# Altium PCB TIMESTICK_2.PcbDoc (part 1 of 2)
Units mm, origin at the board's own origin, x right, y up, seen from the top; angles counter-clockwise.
Board outline 82 x 42 mm, 4 copper layers (Top Layer, Int1, Int2, Bottom Layer), stack 0.954 mm thick; 117 components, 82 nets, 437 pads, 366 vias.
Unrouted connection lines stored in the file: 51.
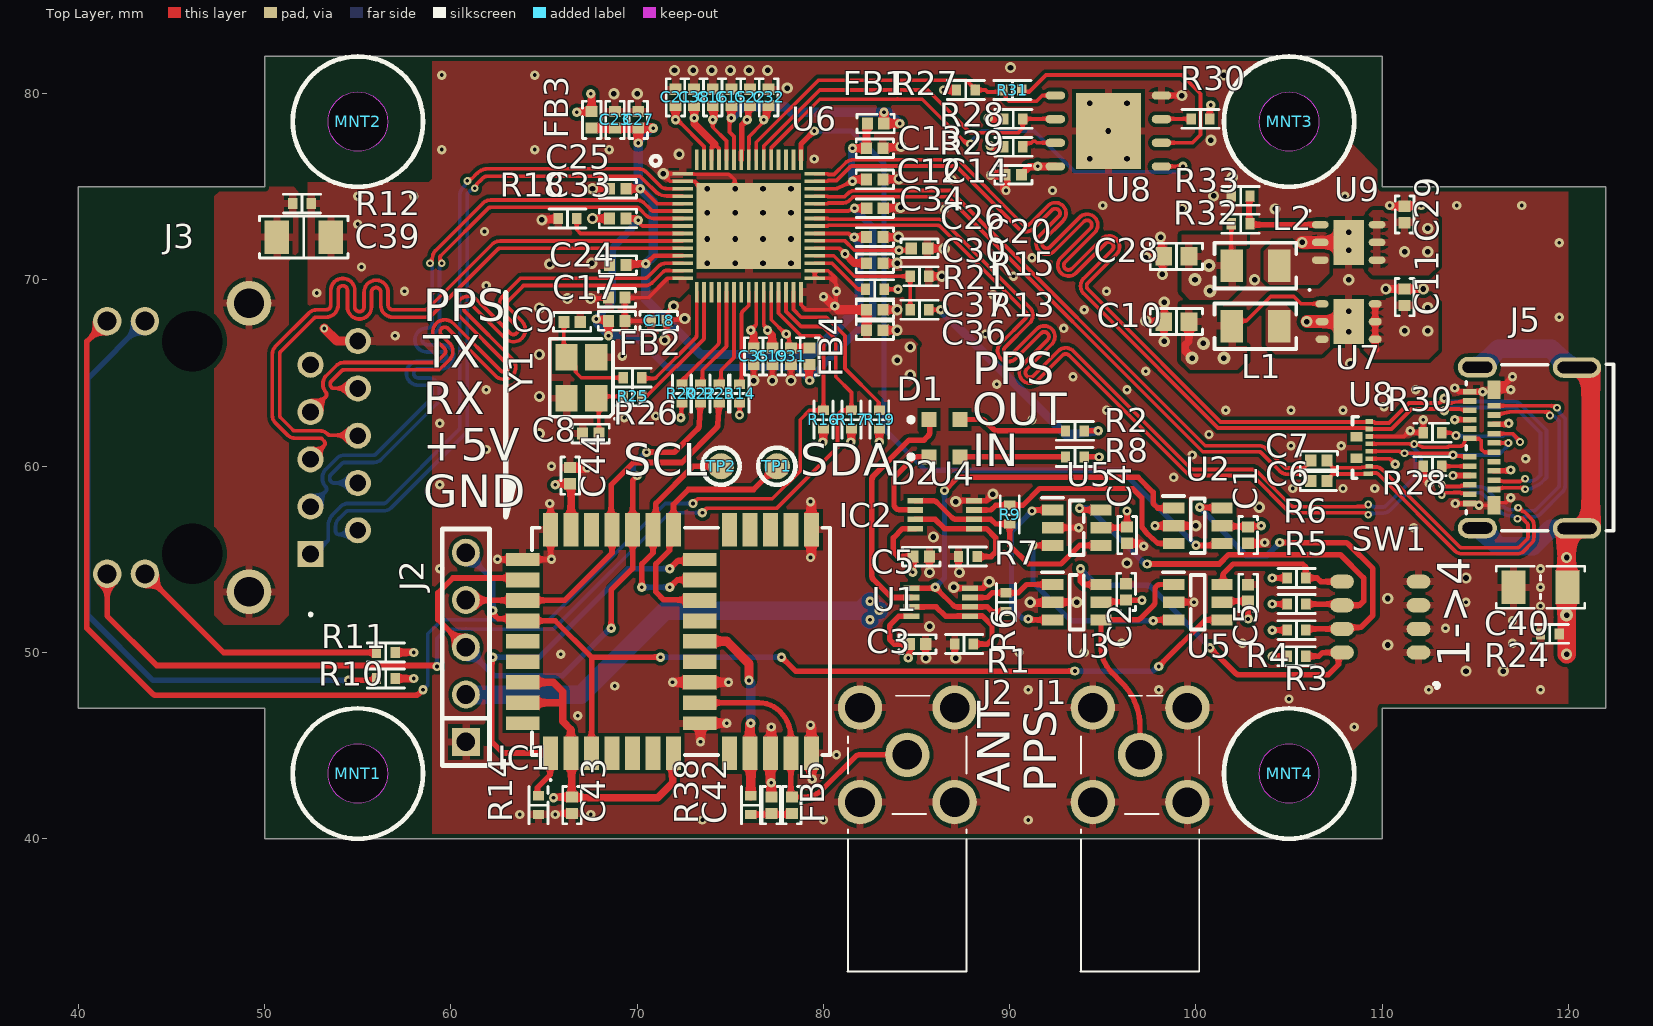
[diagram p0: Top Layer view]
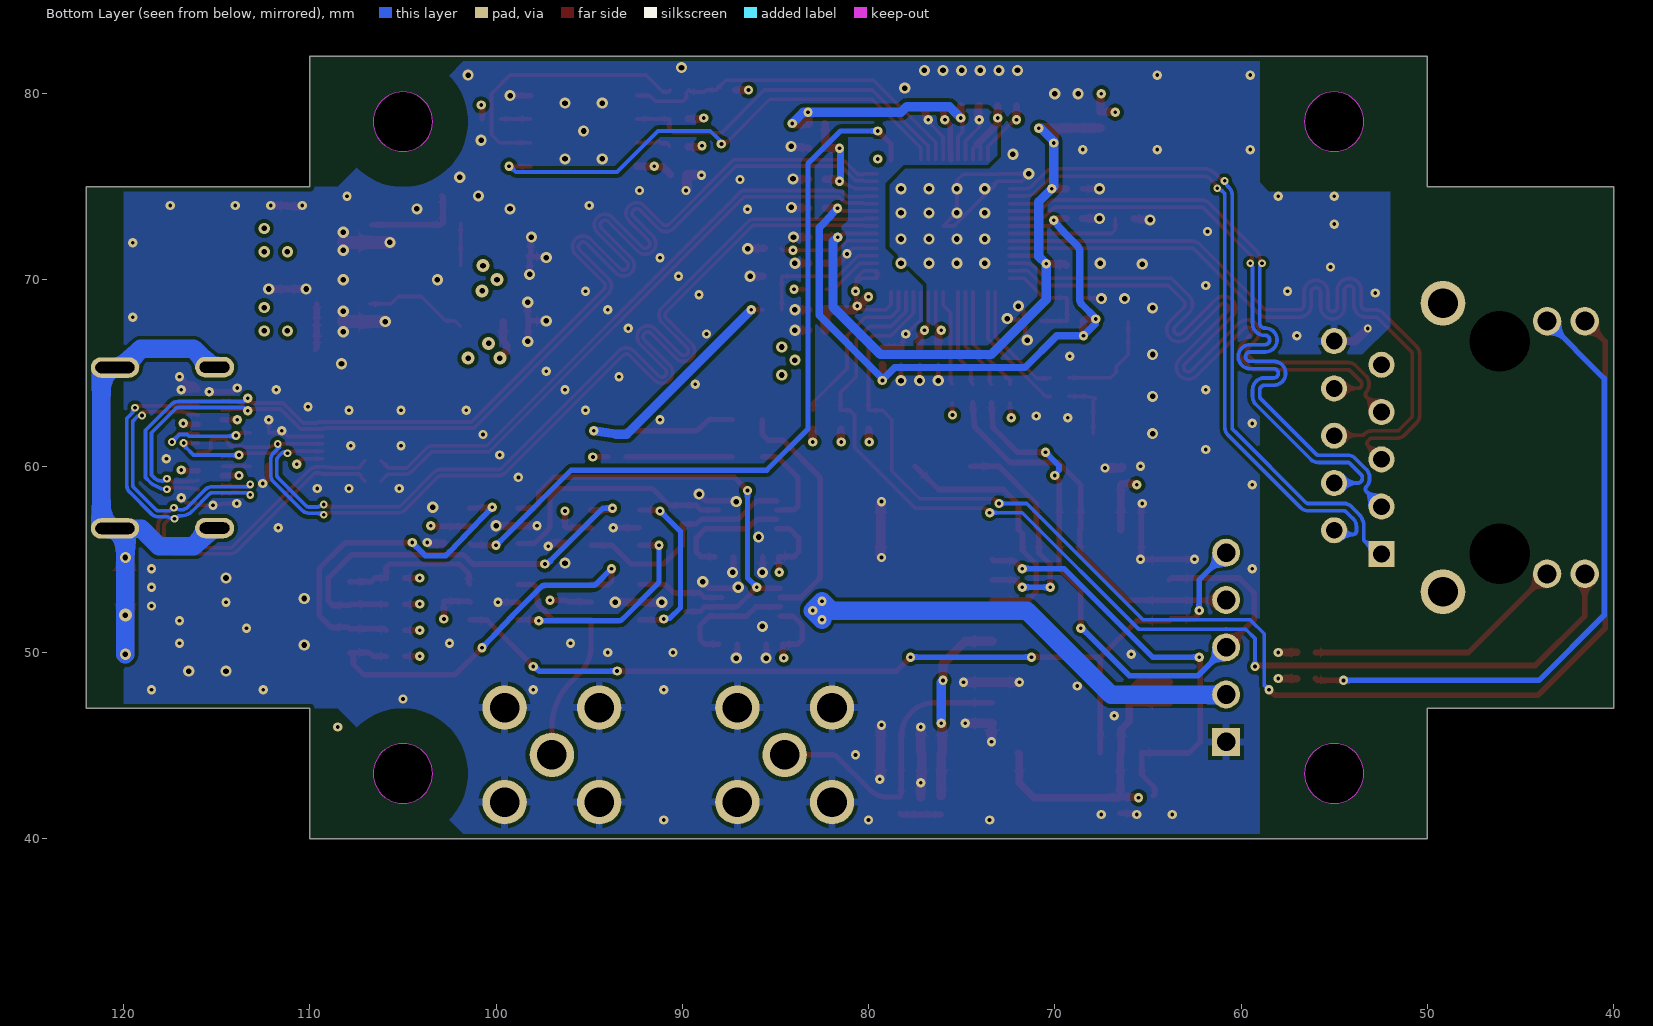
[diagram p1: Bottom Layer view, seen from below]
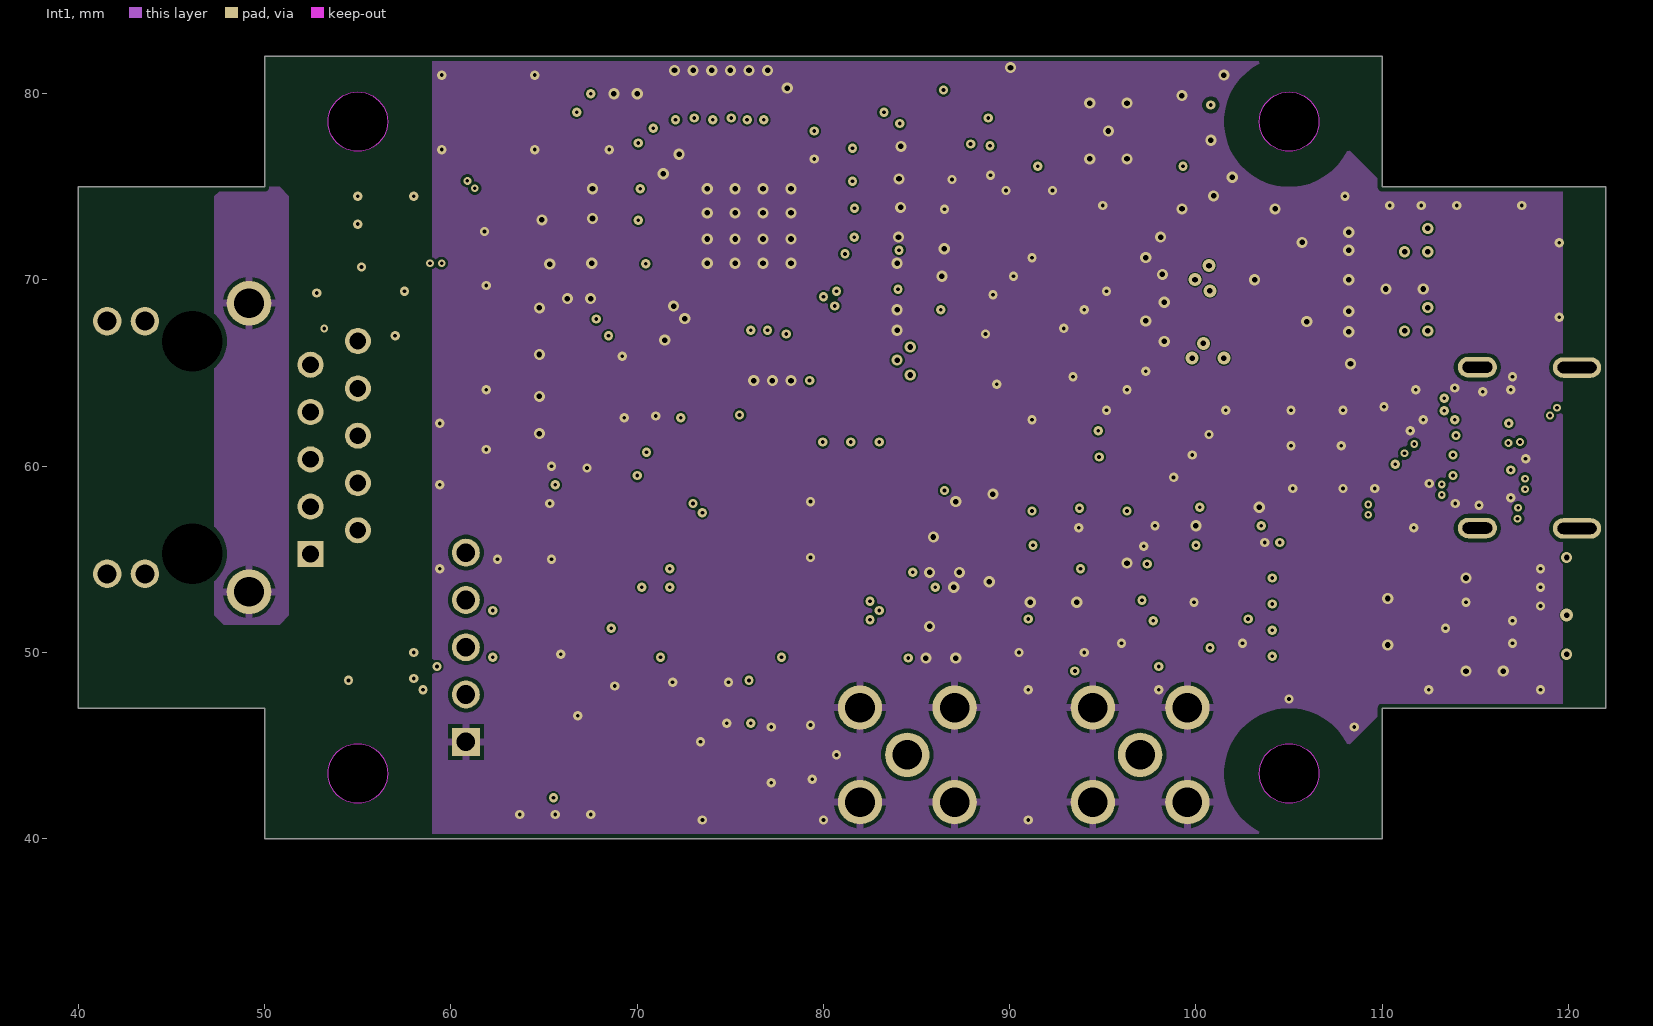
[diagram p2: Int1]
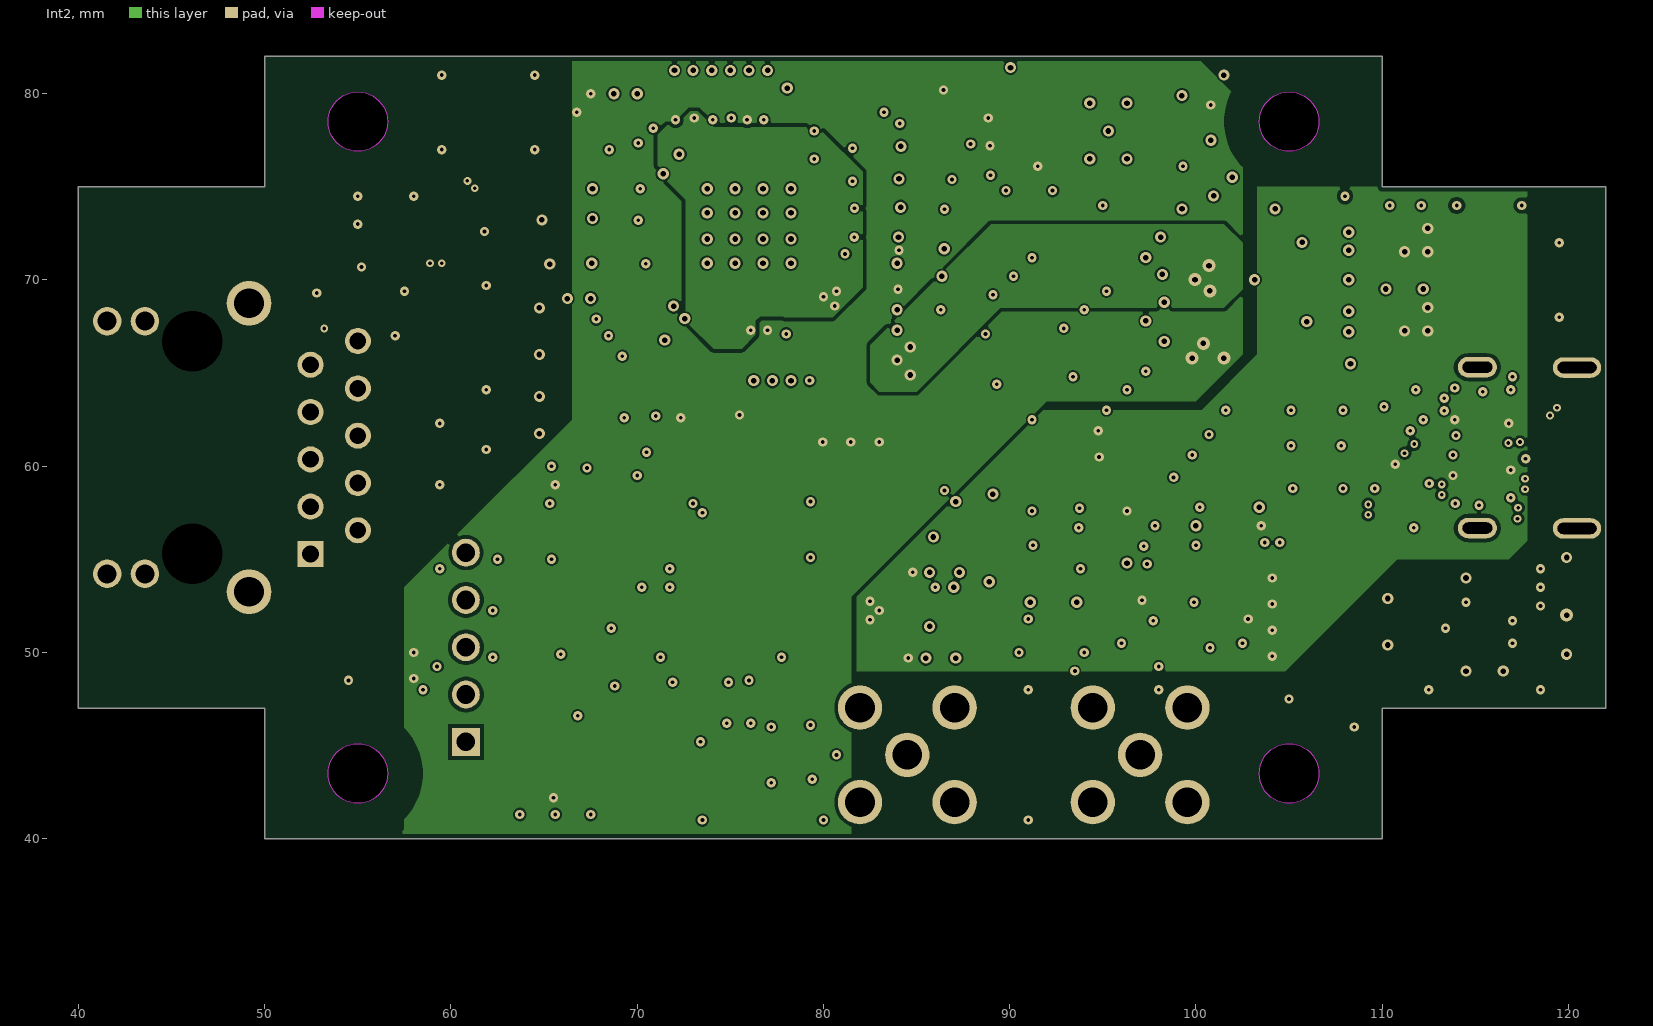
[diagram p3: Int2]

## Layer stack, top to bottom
Top Solder: solder mask 0.0254, SM-001, Dk 3.5
Top Layer: signal copper 0.035
Dielectric 1: prepreg 0.076, FR4, Dk 3.6
Dielectric 2: prepreg 0.076, FR4, Dk 3.6
Int1: signal copper 0.035
Dielectric 3: core 0.51, FR4, Dk 4.6
Int2: signal copper 0.035
Dielectric 4: prepreg 0.076, FR4, Dk 3.6
Dielectric 5: prepreg 0.076, FR4, Dk 3.6
Bottom Layer: signal copper 0.035
Bottom Solder: solder mask 0.0254, SM-001, Dk 3.5

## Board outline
40,47 50,47 50,40 110,40 110,47 122,47 122,75 110,75 110,82 50,82 50,75 40,75

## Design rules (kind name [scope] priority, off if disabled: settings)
AcuteAngle [All] p1: minimum=3.50000000000000E+0001 checktracksonly=FALSE
BoardOutlineClearance "BoardOutlineClearance 1" [All] p1: gap=0.25 ignorepadtopadclearanceinfootprint=FALSE except(0: Arc-SplitContinuation Track-SplitContinuation SMDPad-SplitContinuation THPad-SplitContinuation Via-SplitContinuation Fill-SplitContinuation Poly-SplitContinuation Region-SplitContinuation Text-SplitContinuation) // Milling
BoardOutlineClearance "BoardOutlineClearance 2" [All] p2: gap=0.4 ignorepadtopadclearanceinfootprint=FALSE except(0: Arc-SplitContinuation Track-SplitContinuation SMDPad-SplitContinuation THPad-SplitContinuation Via-SplitContinuation Fill-SplitContinuation Poly-SplitContinuation Region-SplitContinuation Text-SplitContinuation) // V-Cut
Clearance "Clearance 3 Oz" [All] p1 off: gap=0.35 ignorepadtopadclearanceinfootprint=FALSE except(0.25: Arc-Hole Track-Hole SMDPad-Hole THPad-Hole Via-Hole Fill-Hole Poly-Hole Region-Hole Text-Hole)
Clearance "Clearance 2 Oz" [All] p2 off: gap=0.3 ignorepadtopadclearanceinfootprint=FALSE except(0.25: Arc-Hole Track-Hole SMDPad-Hole THPad-Hole Via-Hole Fill-Hole Poly-Hole Region-Hole Text-Hole)
Clearance "Clearance-1 1 Oz" [All] p3 off: gap=0.2 ignorepadtopadclearanceinfootprint=FALSE except(0.25: Arc-Hole Track-Hole SMDPad-Hole THPad-Hole Via-Hole Fill-Hole Poly-Hole Region-Hole Text-Hole) // Standart
Clearance "Clearance-2 1 Oz" [All] p4 off: gap=0.15 ignorepadtopadclearanceinfootprint=FALSE except(0.2: Arc-Fill Arc-Poly Track-Fill Track-Poly SMDPad-Fill SMDPad-Poly THPad-Fill THPad-Poly Via-Fill Via-Poly Fill-Fill Fill-Poly Poly-Poly; 0.25: Arc-Hole Track-Hole SMDPad-Hole THPad-Hole Via-Hole Fill-Hole Poly-Hole Region-Hole Text-Hole) // Advance
Clearance "Clearance-1 1/2 Oz" [All] p5: gap=0.125 ignorepadtopadclearanceinfootprint=FALSE except(0.2: Arc-Fill Arc-Poly Track-Fill Track-Poly SMDPad-SMDPad SMDPad-Fill SMDPad-Poly THPad-Fill THPad-Poly Via-Fill Via-Poly Fill-Fill Fill-Poly Poly-Poly Poly-Region Poly-Text; 0.25: Arc-Hole Track-Hole SMDPad-Hole THPad-Hole Via-Hole Fill-Hole Poly-Hole Region-Hole Text-Hole) // Standart
Clearance "Clearance-2 1/2 Oz" [All] p6 off: gap=0.1 ignorepadtopadclearanceinfootprint=FALSE except(0.15: Arc-Fill Arc-Poly Track-Fill Track-Poly SMDPad-SMDPad SMDPad-Fill SMDPad-Poly THPad-Fill THPad-Poly Via-Fill Via-Poly Fill-Fill Fill-Poly Poly-Poly Poly-Region Poly-Text; 0.25: Arc-Hole Track-Hole SMDPad-Hole THPad-Hole Via-Hole Fill-Hole Poly-Hole Region-Hole Text-Hole) // Advance
DiffPairsRouting "DiffPairsRouting D90" [InDifferentialPairClass('D90')] p1: maxlimit=0.127 minlimit=0.124 mostfreqgap=0.127 toplayer_mingap=0.125 toplayer_maxgap=0.125 toplayer_prefgap=0.125 toplayer_minwidth=0.2 toplayer_maxwidth=0.2 toplayer_prefwidth=0.2 bottomlayer_mingap=0.125 bottomlayer_maxgap=0.125 bottomlayer_prefgap=0.125 bottomlayer_minwidth=0.2 bottomlayer_maxwidth=0.2 bottomlayer_prefwidth=0.2 impedanceprofiledriven=TRUE impedanceprofileid={4E89E9AB-B508-4CAD-8FE7-DB52ABFAAFB0} impedanceprofilevalue=90.000000 maxuncoupledlength=12.7
DiffPairsRouting "DiffPairsRouting D100" [InDifferentialPairClass('D100')] p2: maxlimit=0.203 minlimit=0.127 mostfreqgap=0.203 toplayer_mingap=0.194 toplayer_maxgap=0.194 toplayer_prefgap=0.194 toplayer_minwidth=0.2 toplayer_maxwidth=0.2 toplayer_prefwidth=0.2 bottomlayer_mingap=0.194 bottomlayer_maxgap=0.194 bottomlayer_prefgap=0.194 bottomlayer_minwidth=0.2 bottomlayer_maxwidth=0.2 bottomlayer_prefwidth=0.2 impedanceprofiledriven=TRUE impedanceprofileid={D171256F-88BE-4059-8FC0-C341FC197521} impedanceprofilevalue=100.000000 maxuncoupledlength=12.7
HoleSize "Minimum HoleSize" [IsPad] p1: absolutevalues=TRUE maxlimit=5.9 minlimit=0.6 maxpercent=80.000 minpercent=20.000
HoleSize "Minimum HoleSize VIA 1" [IsVia] p2 off: absolutevalues=TRUE maxlimit=5.9 minlimit=0.3 maxpercent=80.000 minpercent=20.000 // Standart
HoleSize "Minimum HoleSize VIA 2" [IsVia] p3: absolutevalues=TRUE maxlimit=5.9 minlimit=0.2 maxpercent=80.000 minpercent=20.000 // Advance
HoleToHoleClearance Hole2HoleClearance [All] p1: gap=0.25 allowstackedmicrovias=FALSE
MatchedLengths MatchedLengths_USB_DiffPairs_1 [InxSignalClass('USB_CHJ5_1_DL') OR InxSignalClass('USB_CHJ5_1_RX') OR InxSignalClass('USB_CHJ5_1_TX')] p1: tolerance=0.127 checknetsindiffpair=TRUE checkdiffpairvsdiffpair=FALSE checkxsignals=FALSE checkothers=FALSE
MatchedLengths MatchedLengths_USB_DiffPairs [InxSignalClass('USB_CHJ5_1_DL') OR InxSignalClass('USB_CHJ5_1_RX') OR InxSignalClass('USB_CHJ5_1_TX')] p2: tolerance=0.127 checknetsindiffpair=TRUE checkdiffpairvsdiffpair=FALSE checkxsignals=FALSE checkothers=FALSE
MatchedLengths [All] p3: tolerance=25.4 checknetsindiffpair=FALSE checkdiffpairvsdiffpair=TRUE checkxsignals=TRUE checkothers=TRUE
MinimumAnnularRing "Minimum AR VIA Standart" [IsVia] p1 off: minimumring=0.15
MinimumAnnularRing "Minimum AR PAD Standart" [IsPAD] p2 off: minimumring=0.2
MinimumAnnularRing "Minimum AR VIA Advance" [IsVia] p3: minimumring=0.1
MinimumAnnularRing "Minimum AR PAD Advance" [IsPAD] p4: minimumring=0.15
MinimumSolderMaskSliver "SolderMask Bridge Standart" [All] p1 off: minsoldermaskwidth=0.15 // All Masks
MinimumSolderMaskSliver "SolderMask Bridge Advance" [All] p2: minsoldermaskwidth=0.1 // Mask LDI
PlaneClearance "PlaneClearance 3 Oz" [All] p1 off: clearance=0.35
PlaneClearance "PlaneClearance 2 Oz" [All] p2 off: clearance=0.3
PlaneClearance "PlaneClearance 1 Oz" [All] p3 off: clearance=0.2
PlaneClearance "PlaneClearance-1 1/2 Oz" [All] p4: clearance=0.2 // Standart
PlaneClearance "PlaneClearance-2 1/2 Oz" [All] p5 off: clearance=0.15 // Advance
PlaneConnect "TermalConnect 3 Oz" [All] p1: planeconnectstyle=Relief reliefexpansion=0.2 reliefentries=4 reliefconductorwidth=0.35 reliefairgap=0.35 // Standart
PlaneConnect "TermalConnect 2 Oz" [All] p2: planeconnectstyle=Relief reliefexpansion=0.2 reliefentries=4 reliefconductorwidth=0.3 reliefairgap=0.3 // Standart
PlaneConnect "TermalConnect-1 1 Oz" [All] p3: planeconnectstyle=Relief reliefexpansion=0.2 reliefentries=4 reliefconductorwidth=0.2 reliefairgap=0.2 // Standart
PlaneConnect "TermalConnect-2 1 Oz" [All] p4: pad.planeconnectstyle=Relief pad.reliefexpansion=0.15 pad.reliefentries=4 pad.reliefconductorwidth=0.2 pad.reliefairgap=0.2 via.planeconnectstyle=Direct via.reliefexpansion=0.15 via.reliefentries=4 via.reliefconductorwidth=0.15 via.reliefairgap=0.15 // Advance
PlaneConnect "TermalConnect-1 1/2 Oz" [All] p5: planeconnectstyle=Relief reliefexpansion=0.2 reliefentries=4 reliefconductorwidth=0.2 reliefairgap=0.2 // Standart
PlaneConnect "TermalConnect-2 1/2 Oz" [All] p6: pad.planeconnectstyle=Relief pad.reliefexpansion=0.15 pad.reliefentries=4 pad.reliefconductorwidth=0.15 pad.reliefairgap=0.15 via.planeconnectstyle=Direct via.reliefexpansion=0.15 via.reliefentries=4 via.reliefconductorwidth=0.15 via.reliefairgap=0.15 // Advance
PolygonConnect "PolygonConnect 3 Oz" [All] p1 off: thpad.connectstyle=Relief thpad.reliefconductorwidth=0.35 thpad.reliefentries=4 thpad.polygonreliefangle="90 Angle" thpad.airgapwidth=0.35 smdpad.connectstyle=Relief smdpad.reliefconductorwidth=0.35 smdpad.reliefentries=4 smdpad.polygonreliefangle="90 Angle" smdpad.airgapwidth=0.35 via.connectstyle=Direct via.reliefconductorwidth=0.254 via.reliefentries=4 via.polygonreliefangle="90 Angle" via.airgapwidth=0.254
PolygonConnect "PolygonConnect 2 Oz" [All] p2 off: thpad.connectstyle=Relief thpad.reliefconductorwidth=0.3 thpad.reliefentries=4 thpad.polygonreliefangle="90 Angle" thpad.airgapwidth=0.3 smdpad.connectstyle=Relief smdpad.reliefconductorwidth=0.3 smdpad.reliefentries=4 smdpad.polygonreliefangle="90 Angle" smdpad.airgapwidth=0.3 via.connectstyle=Direct via.reliefconductorwidth=0.254 via.reliefentries=4 via.polygonreliefangle="90 Angle" via.airgapwidth=0.254
PolygonConnect "PolygonConnect-1 1 Oz" [All] p3: thpad.connectstyle=Relief thpad.reliefconductorwidth=0.4 thpad.reliefentries=4 thpad.polygonreliefangle="90 Angle" thpad.airgapwidth=0.2 smdpad.connectstyle=Relief smdpad.reliefconductorwidth=0.4 smdpad.reliefentries=4 smdpad.polygonreliefangle="90 Angle" smdpad.airgapwidth=0.2 via.connectstyle=Direct via.reliefconductorwidth=0.254 via.reliefentries=4 via.polygonreliefangle="90 Angle" via.airgapwidth=0.254 // Standart
PolygonConnect "PolygonConnect-2 1 Oz" [All] p4 off: thpad.connectstyle=Relief thpad.reliefconductorwidth=0.15 thpad.reliefentries=4 thpad.polygonreliefangle="90 Angle" thpad.airgapwidth=0.15 smdpad.connectstyle=Relief smdpad.reliefconductorwidth=0.15 smdpad.reliefentries=4 smdpad.polygonreliefangle="90 Angle" smdpad.airgapwidth=0.15 via.connectstyle=Direct via.reliefconductorwidth=0.254 via.reliefentries=4 via.polygonreliefangle="90 Angle" via.airgapwidth=0.254 // Advance
PolygonConnect "PolygonConnect-1 1/2 Oz" [All] p5 off: thpad.connectstyle=Relief thpad.reliefconductorwidth=0.15 thpad.reliefentries=4 thpad.polygonreliefangle="90 Angle" thpad.airgapwidth=0.2 smdpad.connectstyle=Relief smdpad.reliefconductorwidth=0.2 smdpad.reliefentries=4 smdpad.polygonreliefangle="90 Angle" smdpad.airgapwidth=0.2 via.connectstyle=Direct via.reliefconductorwidth=0.254 via.reliefentries=4 via.polygonreliefangle="90 Angle" via.airgapwidth=0.254 // Standart
PolygonConnect "PolygonConnect-2 1/2 Oz" [All] p6 off: thpad.connectstyle=Relief thpad.reliefconductorwidth=0.125 thpad.reliefentries=4 thpad.polygonreliefangle="90 Angle" thpad.airgapwidth=0.15 smdpad.connectstyle=Relief smdpad.reliefconductorwidth=0.125 smdpad.reliefentries=4 smdpad.polygonreliefangle="90 Angle" smdpad.airgapwidth=0.15 via.connectstyle=Direct via.reliefconductorwidth=0.254 via.reliefentries=4 via.polygonreliefangle="90 Angle" via.airgapwidth=0.254 // Advance
RoutingCorners [All] p1 off: cornerstyle=45-Degree minsetback=2.54 maxsetback=2.54
RoutingVias [All] p1: holewidth=0.2 width=0.5 viastyle="Through Hole" minholewidth=0.2 minwidth=0.42 maxholewidth=0.3 maxwidth=0.7
SilkToSilkClearance Silk2SilkClearance [All] p1 off: silktosilkclearance=0.15
SilkToSolderMaskClearance Silk2SolderMaskClearance [IsPad] p1 off: minsilkscreentomaskgap=0.15 clearancetoexposedcopper=TRUE
SolderMaskExpansion SolderMaskExpansion-1 [All] p1: expansion=0.05 istentingtop=FALSE // Standart
SolderMaskExpansion "SolderMaskExpansion LDI" [All] p2: expansion=0.025 istentingtop=FALSE // Advance
UnRoutedNet [All] p1: checkbadconnections=TRUE
Width "Width 3 Oz" [All] p1 off: maxlimit=10 minlimit=0.35 preferedwidth=0.4 checkconnectedcopper=TRUE
Width "Width 2 Oz" [All] p2 off: maxlimit=10 minlimit=0.3 preferedwidth=0.35 minimp=50.000000 maximp=50.000000 favimp=50.000000 checkconnectedcopper=TRUE
Width "Width 1 Oz_S50" [InNetClass('PPS_50')] p3: maxlimit=10 minlimit=0.15 preferedwidth=0.286 toplayer_minwidth=0.286 toplayer_maxwidth=0.286 bottomlayer_minwidth=0.286 bottomlayer_maxwidth=0.286 impedanceprofiledriven=TRUE impedanceprofileid={1FD9FEE7-9353-47D6-AE59-FDB1B434A57E} impedanceprofilevalue=50.000000 minimp=50.000000 maximp=50.000000 favimp=50.000000 checkconnectedcopper=TRUE
Width "Width 1 Oz" [All] p4: maxlimit=1 minlimit=0.2 preferedwidth=0.3 checkconnectedcopper=TRUE
Width "Width 1/2 Oz" [All] p5 off: maxlimit=10 minlimit=0.1 preferedwidth=0.125 checkconnectedcopper=TRUE
20 further rules are at their usual default settings.

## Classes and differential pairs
differential pair class D100: MDI0 MDI1 MDI2 MDI3
differential pair class D90: D SSRX SSTX USB3.0_SSTX
net class USB: D_N D_P SSRX_N SSRX_P SSTX_N SSTX_P USB3.0_SSTX_N USB3.0_SSTX_P
net class MDI: MDI0_N MDI0_P MDI1_N MDI1_P MDI2_N MDI2_P MDI3_N MDI3_P
net class PPS_50: 1PPS_IN 1PPS_IN_BUFF 1PPS_OUT 1PPS_OUT_BUFF 1PPS_SMA_IO 279_1PPS_IO ANT NetU3_3 NetU5_3
differential pair class MDI: MDI0 MDI1 MDI2 MDI3
differential pair class USB: D SSRX SSTX USB3.0_SSTX
component class MAIN: C1 C2 C3 C4 C5 C6 C7 C8 C9 C10 C11 C12 C13 C14 C15 C16 C17 C18 C19 C20 C21 C22 C23 C24 C25 C26 C27 C28 C29 C30 C31 C32 C33 C34 C35 C36 C37 C38 C39 C40 C42 C43 C44 D1 D2 FB1 FB2 FB3 FB4 FB5 IC1 IC2 J1 J2 J3 J5 L1 L2 MNT1 MNT2 MNT3 MNT4 R1 R2 R3 R4 R5 R6 R7 R8 R9 R10 R11 R12 R13 R14 R15 R16 R17 R18 R19 R20 R21 R22 R23 R24 R25 R26 R27 R28 R29 R30 R31 R32 R33 R38 S1 SW1 TP1 TP2 U1 U2 U3 U4 U5 U6 U7 U8 U9 Y1
differential pair MDI0: +MDI0_P -MDI0_N
differential pair USB3.0_SSTX: +USB3.0_SSTX_P -USB3.0_SSTX_N
differential pair SSTX: +SSTX_P -SSTX_N
differential pair SSRX: +SSRX_P -SSRX_N
differential pair MDI3: +MDI3_P -MDI3_N
differential pair MDI2: +MDI2_P -MDI2_N
differential pair MDI1: +MDI1_P -MDI1_N
differential pair D: +D_P -D_N

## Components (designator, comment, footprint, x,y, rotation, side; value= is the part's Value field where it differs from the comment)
C1 "0.1 µF" "CAP 0402_1005" 102.8,56.3 r90 top
C2 "0.1 µF" "CAP 0402_1005" 96.25,53.25 r270 top
C3 "0.1 µF" "CAP 0402_1005" 85.05,50.45 r180 top
C4 "0.1 µF" "CAP 0402_1005" 96.3,56.3 r90 top
C5 "0.1 µF" "CAP 0402_1005" 102.8,53.2 r270 top
C5 "0.1 µF" "CAP 0402_1005" 85.25,55.15 r180 top
C6 "0.1 µF" "CAP 0402_1005" 106.6,59.2 r180 top
C7 "0.1 µF" "CAP 0402_1005" 106.6,60.3 r180 top
C8 "15 pF" "CAP 0402_1005" 67.5,61.75 r0 top
C9 "15 pF" "CAP 0402_1005" 66.5,67.75 r180 top
C10 "22 µF" "CAP 0603_1608" 98.95,67.767 r0 top
C11 "4.7 µF" "CAP 0402_1005" 111.2,69.077 r270 top
C12 "1 µF" "CAP 0402_1005" 82.756,75.4 r180 top
C13 "0.1 µF" "CAP 0402_1005" 82.756,77.075 r180 top
C14 "0.1 µF" "CAP 0402_1005" 90.194,75.65 r0 top
C15 "4.7 µF" "CAP 0402_1005" 75.056,79.8 r270 top
C16 "4.7 µF" "CAP 0402_1005" 74.056,79.8 r270 top
C17 "0.1 µF" "CAP 0402_1005" 68.906,69.05 r0 top
C18 "0.1 µF" "CAP 0402_1005" 71.156,67.8 r180 top
C19 "0.1 µF" "CAP 0402_1005" 77.256,65.9 r90 top
C20 "0.1 µF" "CAP 0402_1005" 85.156,71.7 r180 top
C21 "0.1 µF" "CAP 0402_1005" 72.056,79.8 r270 top
C22 "0.1 µF" "CAP 0402_1005" 76.056,79.8 r270 top
C23 "4.7 µF" "CAP 0402_1005" 68.806,78.6 r270 top
C24 "0.1 µF" "CAP 0402_1005" 68.956,70.8 r0 top
C25 "0.1 µF" "CAP 0402_1005" 68.956,74.9 r0 top
C26 "0.1 µF" "CAP 0402_1005" 82.756,72.3 r180 top
C27 "0.1 µF" "CAP 0402_1005" 70.056,78.6 r270 top
C28 "22 µF" "CAP 0603_1608" 98.95,71.267 r0 top
C29 "4.7 µF" "CAP 0402_1005" 111.2,73.517 r270 top
C30 "0.1 µF" "CAP 0402_1005" 82.756,70.9 r180 top
C31 "0.1 µF" "CAP 0402_1005" 78.256,65.9 r90 top
C32 "0.1 µF" "CAP 0402_1005" 77.056,79.8 r270 top
C33 "0.1 µF" "CAP 0402_1005" 68.956,73.3 r0 top
C34 "0.1 µF" "CAP 0402_1005" 82.766,73.85 r180 top
C35 "0.1 µF" "CAP 0402_1005" 76.256,65.9 r90 top
C36 "0.1 µF" "CAP 0402_1005" 82.756,67.3 r180 top
C37 "0.1 µF" "CAP 0402_1005" 82.756,68.4 r180 top
C38 "0.1 µF" "CAP 0402_1005" 73.056,79.8 r270 top
C39 "1000 pF/2kV" "CAP 1206_3216 - 0.8MM" 52.1,72.3 r0 top
C40 "1000 pF/2kV" "CAP 1206_3216 - 0.8MM" 118.5,53.5 r0 top
C42 "47 pF" "CAP 0402_1005" 77.2,41.8 r270 top
C43 "0.1 µF" "CAP 0402_1005" 66.5,41.8 r90 top
C44 "0.1 µF" "CAP 0402_1005" 66.4,59.5 r270 top
D1 "APT1608ZGCK" FP-APT1608ZGCK-MFG 86.5,62.5 r0 top
D2 "APT1608ZGCK" FP-APT1608ZGCK-MFG 86.5,60.5 r0 top
FB1 "80 Ohms @ 100 MHz" "FER 0402_1005" 82.8,78.4 r180 top
FB2 "80 Ohms @ 100 MHz" "FER 0402_1005" 68.906,67.8 r180 top
FB3 "80 Ohms @ 100 MHz" "FER 0402_1005" 67.556,78.6 r270 top
FB4 "80 Ohms @ 100 MHz" "FER 0402_1005" 79.256,65.9 r270 top
FB5 "80 Ohms @ 100 MHz" "FER 0402_1005" 78.3,41.8 r90 top
IC1 "MAX-F10S-00B" MAXF10S00B 68.6,50.6 r180 top
IC2 "NEO-M9N-00B" NEOM9N00B 72.35,50.6 r270 top
J1 "73100-0114" 731000114 97,44.5 r90 top locked
J2 "PBS-5" PBS-5 60.8,50.28 r90 top
J2 "73100-0114" 731000114 84.5,44.5 r90 top locked
J3 "ARJM11D7-809-AB-EW2" ARJM11D7809ABEW2 52.46,55.29 r270 top locked
J5 "1054500101" "Molex 1054500101" 115.355,61 r90 top locked
L1 "3.3µH" "IND 1008_2520" 103.2,67.517 r180 top
L2 "3.3µH" "IND 1008_2520" 103.2,70.767 r180 top
MNT1 "MOUNT_HOLE" MOUNT_3mm 55,43.5 r0 top locked
MNT2 "MOUNT_HOLE" MOUNT_3mm 55,78.5 r0 top locked
MNT3 "MOUNT_HOLE" MOUNT_3mm 105,78.5 r0 top locked
MNT4 "MOUNT_HOLE" MOUNT_3mm 105,43.5 r0 top locked
R1 "4.7 kOhms" "YAGEO RES 0402_1005" 87.55,50.45 r180 top
R2 "4.7 kOhms" "YAGEO RES 0402_1005" 93.5,61.9 r0 top
R3 "10 kOhms" "YAGEO RES 0402_1005" 105.4,49.8 r180 top
R4 "10 kOhms" "YAGEO RES 0402_1005" 105.4,51.2 r180 top
R5 "10 kOhms" "YAGEO RES 0402_1005" 105.4,52.6 r180 top
R6 "10 kOhms" "YAGEO RES 0402_1005" 105.4,54 r180 top
R6 "0 Ohms" "YAGEO RES 0402_1005" 89.8,52.7 r270 top
R7 "4.7 kOhms" "YAGEO RES 0402_1005" 87.75,55.15 r0 top
R8 "4.7 kOhms" "YAGEO RES 0402_1005" 93.5,60.5 r0 top
R9 "0 Ohms" "YAGEO RES 0402_1005" 90,57.4 r90 top
R10 "330 Ohms" "YAGEO RES 0402_1005" 56.5,48.6 r0 top
R11 "330 Ohms" "YAGEO RES 0402_1005" 56.5,50 r0 top
R12 "1 MOhms" "YAGEO RES 0402_1005" 52,74.1 r0 top
R13 "49.9 kOhms" "YAGEO RES 0402_1005" 85.156,68.4 r0 top
R14 "DNP" "YAGEO RES 0402_1005" 64.7,41.8 r270 top value="0 Ohms"
R14 "10 kOhms" "YAGEO RES 0402_1005" 75.5,63.9 r270 top
R15 "100 kOhms" "YAGEO RES 0402_1005" 85.156,70.2 r180 top
R16 "4.7 kOhms" "YAGEO RES 0402_1005" 80,62.5 r90 top
R17 "4.7 kOhms" "YAGEO RES 0402_1005" 81.5,62.5 r90 top
R18 "24 kOhms" "YAGEO RES 0402_1005" 66.256,73.3 r0 top
R19 "47 kOhms" "YAGEO RES 0402_1005" 83,62.5 r270 top
R20 "47 kOhms" "YAGEO RES 0402_1005" 72.4,63.9 r270 top
R21 "47 kOhms" "YAGEO RES 0402_1005" 82.756,69.5 r0 top
R22 "0 Ohms" "YAGEO RES 0402_1005" 73.4,63.9 r90 top
R23 "0 Ohms" "YAGEO RES 0402_1005" 74.4,63.9 r90 top
R24 "1 MOhms" "YAGEO RES 0402_1005" 119,51 r0 top
R25 "0 Ohms" "YAGEO RES 0402_1005" 69.75,63.75 r0 top
R26 "200 Ohms" "YAGEO RES 0402_1005" 69.75,64.75 r0 top
R27 "4.7 kOhms" "YAGEO RES 0402_1005" 87.644,80.2 r0 top
R28 "5.1 kOhms" "YAGEO RES 0402_1005" 112.7,60 r180 top
R28 "4.7 kOhms" "YAGEO RES 0402_1005" 90.194,78.65 r0 top
R29 "4.7 kOhms" "YAGEO RES 0402_1005" 90.194,77.15 r0 top
R30 "5.1 kOhms" "YAGEO RES 0402_1005" 112.7,61.8 r180 top
R30 "4.7 kOhms" "YAGEO RES 0402_1005" 100.244,78.65 r180 top
R31 "22 Ohms" "YAGEO RES 0402_1005" 90.144,80.2 r180 top
R32 "10 kOhms" "YAGEO RES 0402_1005" 102.4,73.017 r0 top
R33 "39.2 kOhms" "YAGEO RES 0402_1005" 102.4,74.517 r180 top
R38 "33 Ohms" "YAGEO RES 0402_1005" 76.1,41.8 r270 top
SW1 "218-4LPST" "CTS 218-4LPJ" 109.9,51.9 r180 top
TP1 "PAD_TEST" PAD_TEST 77.5,60 r0 top value=.NetName
TP2 "PAD_TEST" PAD_TEST 74.5,60 r0 top value=.NetName
U1 "NC7WZ125K8X" SOP50P310X90-8N 86.3,52.7 r180 top
U2 "SN74LVC1G3157DBVR" SOT95P280X145-6N 100.1,56.8 r0 top
U3 "SN74LVC1G3157DBVR" SOT95P280X145-6N 93.6,52.7 r0 top
U4 "NC7WZ125K8X" SOP50P310X90-8N 86.5,57.4 r180 top
U5 "SN74LVC1G3157DBVR" SOT95P280X145-6N 100.1,52.7 r0 top
U5 "SN74LVC1G3157DBVR" SOT95P280X145-6N 93.6,56.7 r0 top
U6 "AX88279" IC_AX88279 75.991,72.9 r0 top locked
U7 "ST1S06PU33R" DFN6D_L 108.2,67.767 r0 top
U8 "ESD7016MUTAG" ONSC-UDFN-8-517CB_V 108.9,61 r90 top
U8 "SST25VF016B-50-4I-QAF-T" FP-C04-452-MFG 95.3,78 r180 top
U9 "ST1S06PUR" DFN6D_M 108.2,72.017 r0 top
Y1 "25 MHz" "NDK NX3225GA" 67,64.75 r90 top

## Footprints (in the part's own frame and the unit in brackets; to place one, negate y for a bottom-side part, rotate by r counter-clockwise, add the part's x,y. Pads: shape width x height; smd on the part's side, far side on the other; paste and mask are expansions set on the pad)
731000114 [mm]
  round 2.385 hole 1.59: 1(0,0) 2(-2.54,-2.54) 3(-2.54,2.54) 4(2.54,2.54) 5(2.54,-2.54)
  silkscreen extent -11.63,-3.18 3.17,3.2, body extent -11.6,-3.18 3.2,3.18, height 9.57
ARJM11D7809ABEW2 [mm]
  round 2.4 hole 1.6: MH1(2.035,-3.3) MH2(-13.465,-3.3)
  round 1.625 hole 3.25 unplated: MH3(0,-6.35) MH4(-11.43,-6.35)
  rect 1.4x1.4 hole 0.9: P1(0,0)
  round 1.4 hole 0.9: P2(-1.27,2.54) P3(-2.54,0) P4(-3.81,2.54) P5(-5.08,0) P6(-6.35,2.54) P7(-7.62,0) P8(-8.89,2.54) P9(-10.16,0) P10(-11.43,2.54)
  round 1.53 hole 1.02: P11(-12.5,-8.89) P12(-12.5,-10.92) P13(1.07,-8.89) P14(1.07,-10.92)
  silkscreen extent 3.2,-0.05 3.3,0.05, body extent -14.17,-17.2 2.74,4.3, height 14.15
"CAP 0402_1005" [mm] "Chip Capacitor, 2-Leads, Body 1.02x0.51mm, IPC Medium Density"
  rect 0.6x0.64 smd: 1(-0.44,0) 2(0.44,0)
  silkscreen extent -1,-0.5 1,0.5, body extent -0.5,-0.26 0.5,0.26, height 0.52
"CAP 0603_1608" [mm] "Chip Capacitor, 2-Leads, Body 1.60x0.80mm, IPC Medium Density"
  rect 0.9x1 smd: 1(-0.675,0) 2(0.675,0)
  silkscreen extent -1.4,-0.7 1.4,0.7, body extent -0.8,-0.41 0.8,0.41, height 0.82
"CAP 1206_3216 - 0.8MM" [mm] "Chip Capacitor, 2-Leads, Body 3.25x1.60mm, IPC Medium Density"
  rect 1.3x1.8 smd: 1(-1.45,0) 2(1.45,0)
  silkscreen extent -2.37,-1.12 2.37,1.12, body extent -1.6,-0.8 1.6,0.8, height 0.8
"CTS 218-4LPJ" [mm] "DIP, 6 POS, Body 8.79x6.05mm, Pitch 1.27mm, IPC Medium Density"
  oval 1.27x0.76 smd: 1(-2.05,1.905) 2(-2.05,0.635) 3(-2.05,-0.635) 4(-2.05,-1.905) 5(2.05,-1.905) 6(2.05,-0.635) 7(2.05,0.635) 8(2.05,1.905)
  silkscreen extent -3.13,3.55 -2.9,3.79, body extent -3.15,-3.13 3.15,3.12, height 2.71
DFN6D_L [mm] "SON, 6-Leads, Body 3x3mm, Pitch 0.95mm, Thermal Pad 2.4x1.65mm, IPC High Density"
  oval 0.7x0.4 smd: 1(-1.425,0.95) 2(-1.425,0) 3(-1.425,-0.95) 4(1.425,-0.95) 5(1.425,0) 6(1.425,0.95)
  rect 1.65x2.4 smd: 7(0,0)
  silkscreen extent -2.15,1.65 -2.05,1.75, body extent -1.55,-1.55 1.55,1.55, height 0.95
DFN6D_M [mm] "SON, 6-Leads, Body 3x3mm, Pitch 0.95mm, Thermal Pad 2.4x1.65mm, IPC Low Density"
  oval 0.9x0.4 smd: 1(-1.525,0.95) 2(-1.525,0) 3(-1.525,-0.95) 4(1.525,-0.95) 5(1.525,0) 6(1.525,0.95)
  rect 1.65x2.4 smd: 7(0,0)
  silkscreen extent -2.15,1.65 -2.05,1.75, body extent -1.55,-1.55 1.55,1.55, height 0.95
"FER 0402_1005" [mm] "Chip Ferrite, 2-Leads, Body 1.02x0.51mm, IPC Medium Density"
  rect 0.6x0.64 smd: 1(-0.44,0) 2(0.44,0)
  silkscreen extent -1,-0.5 1,0.5, body extent -0.5,-0.26 0.5,0.26, height 0.52
FP-APT1608ZGCK-MFG [mm]
  rect 0.8x0.8 smd paste+0 mask+0: 1(-0.825,0) 2(0.825,0)
  silkscreen extent -1.92,-0.12 -1.67,0.12, body extent -0.8,-0.4 0.8,0.4, height 0.85
FP-C04-452-MFG [mm]
  rrect100% 1.05x0.45 smd paste+0 mask+0: 1(-2.85,1.905) 2(-2.85,0.635) 3(-2.85,-0.635) 4(-2.85,-1.905) 5(2.85,-1.905) 6(2.85,-0.635) 7(2.85,0.635) 8(2.85,1.905)
  rect 3.5x4.1 smd paste+0 mask+0: 9(0,0)
  body extent -3,-2.5 3,2.5, height 0.8
IC_AX88279 [mm]
  rect 1.1x0.2 smd: 1(-3.55,2.8) 2(-3.55,2.4) 3(-3.55,2) 4(-3.55,1.6) 5(-3.55,1.2) 6(-3.55,0.8) 7(-3.55,0.4) 8(-3.55,0) 9(-3.55,-0.4) 10(-3.55,-0.8) 11(-3.55,-1.2) 12(-3.55,-1.6) 13(-3.55,-2) 14(-3.55,-2.4) 15(-3.55,-2.8) 31(3.55,-2.8) 32(3.55,-2.4) 33(3.55,-2) 34(3.55,-1.6) 35(3.55,-1.2) 36(3.55,-0.8) 37(3.55,-0.4) 38(3.55,0) 39(3.55,0.4) 40(3.55,0.8) 41(3.55,1.2) 42(3.55,1.6) 43(3.55,2) 44(3.55,2.4) 45(3.55,2.8)
  rect 0.2x1.1 smd: 16(-2.8,-3.55) 17(-2.4,-3.55) 18(-2,-3.55) 19(-1.6,-3.55) 20(-1.2,-3.55) 21(-0.8,-3.55) 22(-0.4,-3.55) 23(0,-3.55) 24(0.4,-3.55) 25(0.8,-3.55) 26(1.2,-3.55) 27(1.6,-3.55) 28(2,-3.55) 29(2.4,-3.55) 30(2.8,-3.55) 46(2.8,3.55) 47(2.4,3.55) 48(2,3.55) 49(1.6,3.55) 50(1.2,3.55) 51(0.8,3.55) 52(0.4,3.55) 53(0,3.55) 54(-0.4,3.55) 55(-0.8,3.55) 56(-1.2,3.55) 57(-1.6,3.55) 58(-2,3.55) 59(-2.4,3.55) 60(-2.8,3.55)
  rect 5.6x4.6 smd paste-2539.97: 61(0,0)
  silkscreen extent -5.25,3.25 -4.75,3.75, body extent -3.5,-3.5 3.5,3.5, height 0.85
"IND 1008_2520" [mm] "Chip Inductance, 2-leads, Body 2.5x2.1mm, IPC Medium Density"
  rect 1.2x1.75 smd: 1(-1.275,0) 2(1.275,0)
  silkscreen extent -2.18,-1.22 2.2,1.22, body extent -1.3,-1.05 1.3,1.05, height 1
MAXF10S00B [mm]
  rect 1.8x0.7 smd: 1(4.75,-4.4) 9(4.75,4.4) 10(-4.75,4.4) 18(-4.75,-4.4)
  rect 1.8x0.8 smd: 2(4.75,-3.3) 3(4.75,-2.2) 4(4.75,-1.1) 5(4.75,0) 6(4.75,1.1) 7(4.75,2.2) 8(4.75,3.3) 11(-4.75,3.3) 12(-4.75,2.2) 13(-4.75,1.1) 14(-4.75,0) 15(-4.75,-1.1) 16(-4.75,-2.2) 17(-4.75,-3.3)
  body extent -4.85,-5.35 4.85,5.05, height 2.48
"Molex 1054500101" [mm] "USB-C Receptacle Connector 24 Position Surface Mount, 24 Position, Body 8.94x7.90mm"
  rect 0.3x0.7 smd: A1(-3,0.655) A2(-2.5,0.655) A3(-2,0.655) A4(-1.5,0.655) A5(-1,0.655) A6(-0.5,0.655) A7(0.5,0.655) A8(1,0.655) A9(1.5,0.655) A10(2,0.655) A11(2.5,0.655) A12(3,0.655) B2(2.25,-0.645) B3(1.75,-0.645) B4(1.25,-0.645) B5(0.75,-0.645) B6(0.25,-0.645) B7(-0.25,-0.645) B8(-0.75,-0.645) B9(-1.25,-0.645) B10(-1.75,-0.645) B11(-2.25,-0.645)
  rect 1x0.7 smd: B1(3.1,-0.655) B12(-3.1,-0.645)
  oval 1.1x2.6 hole 2.1 slot 0.6 at 0 deg: S(-4.34,-5.105) S(4.3,-5.105)
  oval 1.1x2.1 hole 1.6 slot 0.6 at 0 deg: S(-4.32,0.245) S(4.32,0.245)
  silkscreen extent -4.47,-7.07 4.47,0.83, body extent -4.47,-7.07 4.47,0.83, height 3.21
MOUNT_3mm [mm] "H3/OUT6"
  round 0 hole 3.2 unplated: ""(0,0)
  Keep-Out Layer board cut-out: 0,-1.6 -0.612,-1.478 -1.131,-1.131 -1.478,-0.612 -1.6,0 -1.6,0 -1.478,0.612 -1.131,1.131 -0.612,1.478 0,1.6 0,1.6 0.612,1.478 1.131,1.131 1.478,0.612 1.6,0 1.6,0 1.478,-0.612 1.131,-1.131 0.612,-1.478 0,-1.6
  Multi-Layer pour cut-out: 0,-3.5 -1.339,-3.234 -2.475,-2.475 -3.234,-1.339 -3.5,0 -3.5,0 -3.031,1.75 -1.75,3.031 0,3.5 0,3.5 1.339,3.234 2.475,2.475 3.234,1.339 3.5,0 3.5,0 3.234,-1.339 2.475,-2.475 1.339,-3.234 0,-3.5
  silkscreen extent -3.5,-3.5 3.5,3.5
"NDK NX3225GA" [mm] "Crystal, 4-Leads, Body 2.50x3.20mm, Pitch 2.20mm, IPC Medium Density"
  rect 1.4x1.2 smd: 1(-1.1,-0.8) 2(1.1,-0.8) 3(1.1,0.8) 4(-1.1,0.8)
  silkscreen extent -2.25,-1.85 2.1,1.7, body extent -1.61,-1.26 1.61,1.26, height 0.75
NEOM9N00B [mm]
  rect 1.8x0.8 smd: 1(6,-7) 2(6,-5.9) 3(6,-4.8) 4(6,-3.7) 5(6,-2.6) 6(6,-1.5) 7(6,-0.4) 8(6,2.6) 9(6,3.7) 10(6,4.8) 11(6,5.9) 12(6,7) 13(-6,7) 14(-6,5.9) 15(-6,4.8) 16(-6,3.7) 17(-6,2.6) 18(-6,-0.4) 19(-6,-1.5) 20(-6,-2.6) 21(-6,-3.7) 22(-6,-4.8) 23(-6,-5.9) 24(-6,-7)
  silkscreen extent -6.1,-8 7.5,8, body extent -6.1,-8 6.1,8, height 2.6
ONSC-UDFN-8-517CB_V [mm] "SON, 8-Leads, Body 3.3x1mm, Pitch 0.4mm"
  rect 0.25x0.5 smd: 1(-1.4,-0.35)
  rect 0.25x0.4 smd: 2(-1,-0.4) 3(-0.6,-0.4) 4(-0.2,-0.4) 5(0.2,-0.4) 6(0.6,-0.4) 7(1,-0.4) 8(1.4,-0.4)
  rect 0.5x0.65 smd: 9(0.58,0.275) 10(-0.58,0.275)
  silkscreen extent -1.65,0.18 1.65,0.5, body extent -1.65,-0.5 1.65,0.5, height 0.55
PAD_TEST [mm]
  round 1.4 smd paste-100: 1(0,0)
  silkscreen extent -1,-1 1,1
PBS-5 [mm]
  rect 1.5x1.5 hole 1: 1(-5.08,0)
  round 1.5 hole 1: 2(-2.54,0) 3(0,0) 4(2.54,0) 5(5.08,0)
  silkscreen extent -6.35,-1.27 6.35,1.27, body extent -6.6,-1.25 6.6,1.25, height 8.5
SOP50P310X90-8N [mm]
  rect 0.85x0.3 smd: 1(-1.575,0.75) 2(-1.575,0.25) 3(-1.575,-0.25) 4(-1.575,-0.75) 5(1.575,-0.75) 6(1.575,-0.25) 7(1.575,0.25) 8(1.575,0.75)
  body extent -1.55,-1 1.55,1, height 0.9
SOT95P280X145-6N [mm]
  rect 1.15x0.6 smd: 1(-1.3,0.95) 2(-1.3,0) 3(-1.3,-0.95) 4(1.3,-0.95) 5(1.3,0) 6(1.3,0.95)
  silkscreen extent -1.88,-1.46 0.38,1.6, body extent -1.4,-1.46 1.4,1.46, height 1.45
"YAGEO RES 0402_1005" [mm] "Chip Resistor, 2-Leads, Body 1.0x0.5mm"
  rect 0.5x0.6 smd: 1(-0.5,0) 2(0.5,0)
  silkscreen extent -1,-0.51 1,0.51, body extent -0.5,-0.25 0.5,0.25, height 0.35

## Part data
C1 C2 C3 C4 C5 C5 C6 C7 C13 C14 C17 C18 C19 C20 C21 C22 C24 C25 C26 C27 C30 C31 C32 C33 C34 C35 C36 C37 C38 C43 C44: library part CC0402KRX7R6BB104, "CAP CER 0.1UF 10V X7R 0402", Device Package="0402 (1005 Metric)", Manufacturer=Yageo, Operating Temperature="-55°C ~ 125°C", Supplier Part Number 1=311-1345-1-ND, Temperature Coefficient=X7R, Tolerance=±10%, Voltage - Rated=10V
C8 C9: library part CC0402KRNPO9BN150, "CAP CER 15PF 50V C0G/NPO 0402", Device Package="0402 (1005 Metric)", Manufacturer=Yageo, Operating Temperature="-55°C ~ 125°C", Supplier Part Number 1=311-3780-1-ND, Temperature Coefficient="C0G, NP0", Tolerance=±10%, Voltage - Rated=50V
C10 C28: library part CC0603MRX5R6BB226, "CAP CER 22UF 10V X5R 0603", Device Package="0603 (1608 Metric)", Manufacturer=Yageo, Operating Temperature="-55°C ~ 85°C", Supplier Part Number 1=311-1819-1-ND, Temperature Coefficient=X5R, Tolerance=±20%, Voltage - Rated=10V
C11 C15 C16 C23 C29: library part CC0402MRX5R6BB475, "CAP CER 4.7UF 10V X5R 0402", Device Package="0402 (1005 Metric)", Manufacturer=Yageo, Operating Temperature="-55°C ~ 85°C", Supplier Part Number 1=311-1734-1-ND, Temperature Coefficient=X5R, Tolerance=±20%, Voltage - Rated=10V
C12: library part CC0402KRX5R6BB105, "CAP CER 1UF 10V X5R 0402", Device Package="0402 (1005 Metric)", Manufacturer=Yageo, Operating Temperature="-55°C ~ 85°C", Supplier Part Number 1=311-1439-1-ND, Temperature Coefficient=X5R, Tolerance=±10%, Voltage - Rated=10V
C39 C40: library part CC1206KKX7RDBB102, "CAP CER 1000PF 2KV X7R 1206", Capacitance="1000 pF", Device Package="1206 (3216 Metric)", Manufacturer=Yageo, Operating Temperature="-55°C ~ 125°C", Supplier Part Number 1=311-1487-1-ND, Temperature Coefficient=X7R, Tolerance=±10%, Voltage - Rated="2000V (2kV)"
C42: library part CC0402KRNPO9BN470, "CAP CER 47PF 50V C0G/NPO 0402", Device Package="0402 (1005 Metric)", Manufacturer=Yageo, Operating Temperature="-55°C ~ 125°C", Supplier Part Number 1=311-3783-1-ND, Temperature Coefficient="C0G, NP0", Tolerance=±10%, Voltage - Rated=50V
D1 D2: library part CMP-44529-000024-1, "LED GREEN CLEAR CHIP SMD", Case Code (Imperial)=0603, Case Code (Metric)=1608, Color=Green, Forward Current=20mA, Forward Voltage=3.3V, Lens Color=Colorless, Manufacturer=Kingbright, Max Operating Temperature=85°C, Min Operating Temperature=-40°C, Package Quantity=1, Supplier Part Number=C5554158
FB1 FB2 FB3 FB4 FB5: library part BLM15PD800SN1D, "FERRITE BEAD 80 OHM 0402 1LN", Current Rating (Max)=1.5A, DC Resistance (DCR) (Max)=70mOhm, Device Package="0402 (1005 Metric)", Manufacturer="Murata Electronics", Operating Temperature="-55°C ~ 125°C", Supplier Part Number 1=490-5202-1-ND
IC1: "Integrated Circuit", Manufacturer_Name=u-blox
IC2: "Integrated Circuit", Manufacturer_Name=u-blox, Mouser Part Number=377-NEO-M9N-00B
J1 J2: "Connector", Manufacturer_Name=Molex, Mouser Part Number=538-73100-0114
J2: "Connector", Manufacturer=Connfly, Part Number=PBD-5, Part Number1=DS-1023-1x5
J3: "Connector", Manufacturer_Name=ABRACON, Mouser Part Number=815-RJM11D7809ABEW2
J5: "CONN RCP USB3.1 TYPEC 24P SMD RA", Current Rating (Amps)="0.25A, 1A, 5A", Manufacturer=Molex, Operating Temperature="-30°C ~ 85°C", Supplier Part Number 1=WM12856CT-ND, Voltage - Rated=30VAC/DC
L1 L2: library part LQM2HPN3R3MG0L, "FIXED IND 3.3UH 1.2A 100 MOHM", Current Rating (Amps)=1.2A, DC Resistance (DCR)="125mOhm Max", Device Package="1008 (2520 Metric)", Frequency - Self Resonant=30MHz, Inductance Frequency - Test=1MHz, Manufacturer="Murata Electronics", Operating Temperature="-55°C ~ 125°C", Supplier Part Number 1=490-5115-1-ND, Tolerance=±20%
MNT1 MNT2 MNT3 MNT4: "Mount hole"
R1 R2 R7 R8 R16 R17 R27 R28 R29 R30: library part RC0402FR-074k7L, "RES 4.7K OHM 1% 1/16W 0402", Device Package="0402 (1005 Metric)", Manufacturer=Yageo, Operating Temperature="-55°C ~ 155°C", Part Number=RC0402FR-074K7L, Power (Watts)="0.063W, 1/16W", Supplier Device Package=0402, Supplier Part Number 1=311-4.7KLRCT-ND, Temperature Coefficient=±100ppm/°C, Tolerance=±1%
R3 R4 R5 R6 R14 R32: library part RC0402FR-0710KL, "RES 10K OHM 1% 1/16W 0402", Device Package="0402 (1005 Metric)", Manufacturer=Yageo, Operating Temperature="-55°C ~ 155°C", Power (Watts)="0.063W, 1/16W", Supplier Device Package=0402, Supplier Part Number 1=311-10.0KLRCT-ND, Temperature Coefficient=±100ppm/°C, Tolerance=±1%
R6 R9 R22 R23 R25: library part RC0402FR-070RL, "RES 0 OHM JUMPER 1/16W 0402", Device Package="0402 (1005 Metric)", Manufacturer=Yageo, Operating Temperature="-55°C ~ 155°C", Power (Watts)="0.063W, 1/16W", Supplier Device Package=0402, Supplier Part Number 1=311-0.0LRCT-ND, Tolerance=Jumper
R10 R11: library part RC0402FR-07330RL, "RES 330 OHM 1% 1/16W 0402", Device Package="0402 (1005 Metric)", Manufacturer=Yageo, Operating Temperature="-55°C ~ 155°C", Power (Watts)="0.063W, 1/16W", Supplier Device Package=0402, Supplier Part Number 1=311-330LRCT-ND, Temperature Coefficient=±100ppm/°C, Tolerance=±1%
R12 R24: library part RC0402FR-071ML, "RES 1M OHM 1% 1/16W 0402", Device Package="0402 (1005 Metric)", Manufacturer=Yageo, Operating Temperature="-55°C ~ 155°C", Power (Watts)="0.063W, 1/16W", Supplier Device Package=0402, Supplier Part Number 1=311-1.00MLRCT-ND, Temperature Coefficient=±100ppm/°C, Tolerance=±1%
R13: library part RC0402FR-0749K9L, "RES 49.9K OHM 1% 1/16W 0402", Device Package="0402 (1005 Metric)", Manufacturer=Yageo, Operating Temperature="-55°C ~ 155°C", Power (Watts)="0.063W, 1/16W", Supplier Device Package=0402, Supplier Part Number 1=311-49.9KLRCT-ND, Temperature Coefficient=±100ppm/°C, Tolerance=±1%
R14: library part RC0402FR-070RL, "RES 0 OHM JUMPER 1/16W 0402", Device Package="0402 (1005 Metric)", Manufacturer=Yageo, Operating Temperature="-55°C ~ 155°C", Power (Watts)="0.063W, 1/16W", Resistance="0 Ohms", Supplier Device Package=0402, Supplier Part Number 1=311-0.0LRCT-ND, Tolerance=Jumper
R15: library part RC0402FR-07100KL, "RES 100K OHM 1% 1/16W 0402", Device Package="0402 (1005 Metric)", Manufacturer=Yageo, Operating Temperature="-55°C ~ 155°C", Power (Watts)="0.063W, 1/16W", Supplier Device Package=0402, Supplier Part Number 1=311-100KLRCT-ND, Temperature Coefficient=±100ppm/°C, Tolerance=±1%
R18: library part RC0402FR-0724KL, "RES 24K OHM 1% 1/16W 0402", Device Package="0402 (1005 Metric)", Manufacturer=Yageo, Operating Temperature="-55°C ~ 155°C", Power (Watts)="0.063W, 1/16W", Supplier Device Package=0402, Supplier Part Number 1=311-24KLRCT-ND, Temperature Coefficient=±100ppm/°C, Tolerance=±1%
R19 R20 R21: library part RC0402FR-0747KL, "RES 47K OHM 1% 1/16W 0402", Device Package="0402 (1005 Metric)", Manufacturer=Yageo, Operating Temperature="-55°C ~ 155°C", Power (Watts)="0.063W, 1/16W", Supplier Device Package=0402, Supplier Part Number 1=311-47.0KLRCT-ND, Temperature Coefficient=±100ppm/°C, Tolerance=±1%
R26: library part RC0402FR-07200RL, "RES 200 OHM 1% 1/16W 0402", Device Package="0402 (1005 Metric)", Manufacturer=Yageo, Operating Temperature="-55°C ~ 155°C", Power (Watts)="0.063W, 1/16W", Supplier Device Package=0402, Supplier Part Number 1=311-200LRCT-ND, Temperature Coefficient=±100ppm/°C, Tolerance=±1%
R28 R30: library part RC0402FR-075k1L, "RES 5.1K OHM 1% 1/16W 0402", Device Package="0402 (1005 Metric)", Manufacturer=Yageo, Operating Temperature="-55°C ~ 155°C", Part Number=RC0402FR-075K1L, Power (Watts)="0.063W, 1/16W", Supplier Device Package=0402, Supplier Part Number 1=311-5.10KLRCT-ND, Temperature Coefficient=±100ppm/°C, Tolerance=±1%
R31: library part RC0402FR-0722RL, "RES 22 OHM 1% 1/16W 0402", Device Package="0402 (1005 Metric)", Manufacturer=Yageo, Operating Temperature="-55°C ~ 155°C", Power (Watts)="0.063W, 1/16W", Supplier Device Package=0402, Supplier Part Number 1=311-22.0LRCT-ND, Temperature Coefficient=±100ppm/°C, Tolerance=±1%
R33: library part RC0402FR-0739K2L, "RES 39.2K OHM 1% 1/16W 0402", Device Package="0402 (1005 Metric)", Manufacturer=Yageo, Operating Temperature="-55°C ~ 155°C", Power (Watts)="0.063W, 1/16W", Supplier Device Package=0402, Supplier Part Number 1=311-39.2KLRCT-ND, Temperature Coefficient=±100ppm/°C, Tolerance=±1%
R38: library part RC0402FR-0733RL, "RES 33 OHM 1% 1/16W 0402", Device Package="0402 (1005 Metric)", Manufacturer=Yageo, Operating Temperature="-55°C ~ 155°C", Power (Watts)="0.063W, 1/16W", Supplier Device Package=0402, Supplier Part Number 1=311-33.0LRCT-ND, Temperature Coefficient=±100ppm/°C, Tolerance=±1%
SW1: "SWITCH SLIDE DIP SPST 25MA 24V", Current Rating (Amps)=25mA, Manufacturer="CTS Electrocomponents", Operating Temperature="-55°C ~ 85°C", Supplier Part Number 1=CT2184LPST-ND, Voltage Rating=24VDC
TP1 TP2: "Test Point", Case={Case}, Manufacturer={Manufacturer}, PowerVoltage={PowerVoltage}, Tempcoeff={Tempcoeff}, Tolerance={Tolerance}
U1 U4: "Integrated Circuit", Manufacturer_Name=onsemi
U2 U3 U5 U5: "Integrated Circuit", Manufacturer_Name="Texas Instruments", Mouser Part Number=595-SN74LVC1G3157DBV
U6: library part IC_AX88279
U7: library part CMP-0240-00158-1, "Synchronous rectification with inhibit, 1.5 A, 1.5 MHz adjustable, step-down switching regulator, 6-Pin DFN", Case/Package=DFN, Frequency=1.5MHz, Manufacturer=STMicroelectronics, Max Operating Temperature=125°C, Max Output Current=1.5A, Max Supply Voltage=6V, Min Input Voltage=2.7V, Min Operating Temperature=-30°C, Output Voltage=3.3V, Package Quantity=1, Quiescent Current=1.5mA, Supplier Part Number=497-6311-1-ND
U8: library part CMP-1063-00263-1, "Low Capacitance ESD Protection USB 3.0, 8-Pin UDFN, Pb-Free, Tape and Reel", Manufacturer="On Semiconductor"
U8: library part CMP-00252-18686437-1, "SST25VF016B-50-4I-QAF-T Flash Serial-SPI 3.3V 16Mbit 2M x 8bit 8ns 8-Pin WSON EP T/R - Tape and Reel", Frequency=50MHz, Max Operating Temperature=85°C, Max Supply Voltage=3.6V, Min Operating Temperature=-40°C, Min Supply Voltage=2.7V, Nominal Supply Current=15mA, Operating Supply Voltage=3.3V
U9: library part CMP-0240-00159-1, "Synchronous rectification with inhibit, 1.5 A, 1.5 MHz adjustable, step-down switching regulator, 6-Pin DFN"
Y1: library part NX3225GA-25.000M-STD-CRG-2, "CRYSTAL 25.0000MHZ 8PF SMD", ESR (Equivalent Series Resistance)="50 Ohms", Frequency Stability=±30ppm, Frequency Tolerance=±20ppm, Load Capacitance=8pF, Manufacturer="NDK America, Inc.", Operating Mode=Fundamental, Operating Temperature="-40°C ~ 85°C", Package / Case="4-SMD, No Lead", Supplier Part Number 1=644-1259-1-ND

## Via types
v1: diameter 0.5, hole 0.2, Top Layer to Bottom Layer, tented both sides, 226 vias
v2: diameter 0.6, hole 0.3, Top Layer to Bottom Layer, tented both sides, 105 vias
v3: diameter 0.42, hole 0.2, Top Layer to Bottom Layer, tented both sides, 19 vias
v4: diameter 0.6, hole 0.3, Top Layer to Bottom Layer, 9 vias
v5: diameter 0.7, hole 0.3, Top Layer to Bottom Layer, tented both sides, 7 vias

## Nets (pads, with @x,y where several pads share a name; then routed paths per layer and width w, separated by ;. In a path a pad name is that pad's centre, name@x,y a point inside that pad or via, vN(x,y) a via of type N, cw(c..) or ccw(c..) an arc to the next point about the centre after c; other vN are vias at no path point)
1PPS_IN: R9.1 U4.2 U4.5 U5.4@94.9,55.75 | length 12.4
  Top Layer w0.286: U4.5@84.925,58.15 85.882,58.15 cw(c85.882,57.864) 86.083,58.067 86.917,57.233 ccw(c87.118,57.436) 87.118,57.15 U4.2@88.075,57.15 89,57.15 89.25,56.9 R9.1@90,56.9 90,55.75 91,54.75 92.75,54.75 93.75,55.75 U5.4@94.9,55.75
1PPS_IN_BUFF: R9.2 U2.3 U4.3 | length 13.3
  Top Layer w0.286: U4.3@88.075,57.65 89,57.65 89.25,57.9 R9.2@90,57.9 90.7,57.9 91.6,58.8 96.6,58.8 97.1,58.3 97.1,56.818 ccw(c97.386,56.818) 97.184,56.616 97.216,56.584 cw(c97.013,56.383) 97.257,56.532 ccw(c97.7,56.8) 97.346,56.422 97.873,55.927 ccw(c98.068,56.136) 98.068,55.85 U2.3@98.8,55.85
1PPS_IN_LED: D2.1 U4.6 | length 5.1
  Top Layer w0.286: U4.6@84.925,57.65 84.643,57.657 84.064,57.671 cw(c84.072,57.957) 83.785,57.957 83.785,59.267 cw(c84.072,59.267) 83.87,59.47 84.816,60.416 cw(c85.018,60.214) 85.018,60.5 D2.1@85.675,60.5
1PPS_OUT: R6.2@89.8,52.2 U1.2 U1.5 U2.1 | length 24.6
  Top Layer w0.286: U1.5@84.725,53.45 85.932,53.45 cw(c85.932,53.164) 86.133,53.367 86.967,52.533 ccw(c87.168,52.736) 87.168,52.45 88.8,52.45 89.05,52.2 R6.2@89.8,52.2 ; v1(86.5,58.7) 87.2,59.4 96.9,59.4 97.7,58.6 97.7,58 97.95,57.75 U2.1@98.8,57.75
  Bottom Layer w0.286: v1(86,53.5) 86.5,54 v1(86.5,58.7)
1PPS_OUT_BUFF: R6.1@89.8,53.2 U1.3 U3.1 | length 4.8
  Top Layer w0.286: U1.3@87.875,52.95 88.8,52.95 89.05,53.2 R6.1@89.8,53.2 ; R6.1@89.85,53.15 R6.1@89.8,53.2 ; U3.1@92.3,53.65 90.9,53.65 90.45,53.2 R6.1@89.8,53.2
1PPS_OUT_LED: D1.1 U1.6 | length 12.8
  Top Layer w0.3: 82.687,53.913 cw(c82.9,54.124) 82.6,54.124 82.6,59.276 cw(c82.9,59.276) 82.688,59.488 84.6,61.4 85.4,61.4 85.613,61.613 ccw(c85.4,61.824) 85.7,61.824 D1.1@85.7,62.5 ; 82.688,53.912 83.65,52.95 U1.6@84.725,52.95
1PPS_SMA_IO: J1.1 U3.4 U5.1@98.8,53.65 | length 13
  Top Layer w0.286: 94.9,50.327 ccw(c96.898,50.327) 95.481,48.919 95.482,48.918 96.011,48.389 ; 94.9,50.329 94.9,51.593 U3.4@94.9,51.75 96.832,51.75 ccw(c96.832,52.036) 97.033,51.833 97.717,52.517 ccw(c97.514,52.718) 97.8,52.718 97.8,53.364 cw(c98.086,53.364) 98.086,53.65 U5.1@98.8,53.65 ; 96.011,48.389 cw(c93.58,45.984) 97,45.988 J1.1@97,44.5
279_1PPS_IO: U2.4 U6.46 | length 41.3
  Top Layer w0.286: U6.46@78.791,76.45 78.791,77.291 v1(79.5,78) ; v1(100,55.75) 101.3,55.75 U2.4@101.4,55.85
  Bottom Layer w0.286: v1(79.5,78) 81.5,78 83.25,76.25 83.25,62 85.468,59.782 95.968,59.782 v1(100,55.75)
279_TOD_IN: IC1.2 IC2.20 J2.3@60.8,50.28 R22.1 | length 33.1
  Top Layer w0.3: J2.3@60.8,50.26 59.3,51.76 59.3,53.2 60.1,54 63.75,54 IC1.2@63.85,53.9 ; v1(68.6,51.3) 68.6,53.35 69.75,54.5 IC2.20@69.75,56.6 69.75,59.224 70,59.474 v1(70,59.5) ; v1(70.5,60.75) 72,60.75 73.24,61.99 ccw(c73.028,62.202) 73.327,62.184 73.394,63.3 R22.1@73.4,63.4
  Bottom Layer w0.3: J2.3@60.8,50.26 62.31,48.75 65.996,48.75 68.546,51.3 v1(68.6,51.3) ; v1(70,59.5) 70,59.55 69.774,59.776 69.774,60.024 v1(70.5,60.75)
279_TOD_IN_R: R22.2 U6.20 | length 5.5
  Top Layer w0.2: R22.2@73.4,64.4 73.5,64.55 73.5,65.061 cw(c73.7,65.061) 73.559,65.203 74.791,66.435 U6.20@74.791,69.35
279_TOD_OUT: IC1.3 IC2.21 J2.4@60.8,52.82 R23.1 | length 20.9
  Top Layer w0.3: J2.4@60.8,52.8 IC1.3@63.85,52.8 66.1,52.8 68.65,55.35 IC2.21@68.65,56.65 ; IC2.21@68.65,56.6 68.6,56.65 68.6,59 69.8,60.2 72.4,60.2 74.243,62.043 ccw(c74.031,62.255) 74.33,62.237 74.394,63.3 R23.1@74.4,63.4
279_TOD_OUT_R: R23.2 U6.21 | length 5.3
  Top Layer w0.2: R23.2@74.4,64.4 74.5,64.55 74.5,65.061 cw(c74.7,65.061) 74.559,65.203 75.191,65.835 U6.21@75.191,69.35
ANT: FB5.2 IC1.11 IC2.11 J2.1@84.5,44.5 | length 16
  Top Layer w0.286: IC1.11@73.35,47.3 74.107,47.3 76.525,47.3 cw(c76.525,45.67) 77.677,46.823 cw(c76.283,45.435) 78.25,45.438 78.25,45.357 78.25,42.397 FB5.2@78.3,42.24 ; FB5.2@78.4,42.24 78.477,42.24 79.015,42.24 ccw(c79.014,43.511) 79.909,42.609 ; 79.909,42.609 81.717,44.417 cw(c81.918,44.214) 81.918,44.5 J2.1@84.335,44.5
AVDD10: C12.2 C13.2 FB1.2 U6.43 | length 6.8
  Top Layer w0.203: U6.43@79.541,74.9 80.672,74.9 ccw(c80.672,75.103) 80.759,74.92 v1(81.556,75.3)
  Top Layer w0.4: v1(81.556,75.3) 81.656,75.4 C12.2@82.316,75.4 ; v1(81.556,77.075) C13.2@82.316,77.075 82.316,78.356 FB1.2@82.36,78.4
  Bottom Layer w0.4: v1(81.556,75.3) cw(c81.906,75.494) 81.506,75.494 81.506,76.883 cw(c81.906,76.881) v1(81.556,77.075)
AVDD_1.85: C33.2 C34.2 FB2.2 FB4.2 U6.8 U6.40 | length 38.6
  Top Layer w0.2: v1(70.056,73.2) 70.055,73.19 ccw(c70.255,73.185) 70.113,73.044 70.198,72.958 ccw(c70.339,73.1) 70.339,72.9 70.605,72.9 71.991,72.9 U6.8@72.441,72.9 ; U6.40@79.541,73.7 81.298,73.7 ccw(c81.298,73.9) 81.424,73.745 ; 81.424,73.745 cw(c81.549,73.589) 81.456,73.766 81.573,73.827 cw(c81.666,73.65) v1(81.666,73.85)
  Top Layer w0.4: v1(67.8,67.9) 67.819,67.881 68.385,67.881 FB2.2@68.466,67.8 68.456,67.79 v1(68.456,67) ; C33.2@69.396,73.3 69.793,73.3 cw(c69.791,72.9) v1(70.056,73.2) ; v1(79.256,64.6) 79.256,64.627 79.225,64.658 79.225,65.429 FB4.2@79.256,65.46 ; v1(81.666,73.85) C34.2@82.326,73.85
  Bottom Layer w0.4: v1(70.056,73.2) 69.526,72.583 69.519,72.574 cw(c69.215,72.835) 69.51,72.564 69.403,72.448 cw(c69.109,72.719) 69.391,72.435 68.773,71.817 ccw(c69.056,71.534) 68.656,71.534 68.656,68.966 cw(c68.256,68.966) 68.539,68.683 67.85,67.994 67.85,67.977 67.8,67.927 v1(67.8,67.9) 67.819,67.881 67.819,67.637 v1(68.456,67) 69.9,67 71.6,65.3 78.587,65.3 79.206,64.681 79.206,64.677 79.256,64.627 v1(79.256,64.6) ; v1@79.26,64.631 79.275,64.646 79.275,64.719 82.656,68.1 82.656,72.8 82.333,73.123 82.332,73.124 cw(c82.616,73.406) 82.318,73.138 ccw(c82.022,72.869) 82.317,73.14 v1(81.666,73.85)
AVDD_33: C23.2 C24.2 C25.2 C26.2 C27.2 FB3.2 U6.5 U6.12 U6.37 | length 41.2
  Top Layer w0.2: v1(70.156,74.9) 70.237,74.9 70.376,74.761 70.395,74.761 71.056,74.1 U6.5@72.441,74.1 ; U6.37@79.541,72.5 81.356,72.5 81.556,72.3 v1(81.656,72.3)
  Top Layer w0.25: v1(70.459,70.864) 70.472,70.864 70.908,71.3 U6.12@72.441,71.3
  Top Layer w0.4: C24.2@69.396,70.8 69.46,70.864 v1(70.459,70.864) ; C25.2@69.396,74.9 v1(70.156,74.9) ; v1(81.656,72.3) C26.2@82.316,72.3
  Top Layer w0.5: FB3.2@67.556,78.16 C23.2@68.806,78.16 C27.2@70.056,78.16 ; v1(70.056,77.35) C27.2@70.056,78.16 ; v1(70.856,78.15) 70.846,78.16 C27.2@70.056,78.16
  Bottom Layer w0.5: v1(70.056,77.35) 70.056,75 v1(70.156,74.9) 70.856,74.2 70.856,71.261 v1(70.459,70.864) 70.459,68.948 73.407,66 79.356,66 81.906,68.55 81.906,72.05 v1(81.656,72.3) ; v1@70.056,77.45 70.756,78.15 v1(70.856,78.15)
CHASSIS_GND: C39.1 J3.MH1 J3.MH2 R12.1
